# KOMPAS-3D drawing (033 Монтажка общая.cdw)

Referenced files in \\Promsrv4\спо\002_Проекты (ПСПД)\г. Тверь\Проекты жилые дома\Бобкова, 37\: Монтажка общая лист 55А.cdw
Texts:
  ПСПД-0000-2015
  Узел учета тепловой энергии, теплоносителя
  Ду65
  Ду50
  ИУСОп-65фс-50П-65фс-Ф65-01
  ИУСОо-65фс-50П-65фс-Ф65-01
  Направление потока**
  Стандартные изделия
  Переход К-57x5-32x3 ГОСТ 17378-2001
  Прокладка А-25-16-ПОН ГОСТ 15180-86
  Болт М6-6gx10.21.12Х18Н10Т ГОСТ 7798-70
  Переход
  ГОСТ 17378-2001
  Прокладка
  ГОСТ 15180-86
  А-25-16-ПОН
  Болт
  ГОСТ 7798-70
  М6-6gx10.21.12Х18Н10Т
  Узел учета тепловой энергии,
  теплоносителя
  Монтажный чертеж
  ЗАО "ПромСервис"
  ПСПД-0022-2015-
  Разраб.
  Чертеж строит. Первый лист. ГОСТ Р 21.1101-2009 Ф4.
  Лит-Масса-Масштаб
  Материал-Предприятие
  Масштаб
  Изм.
  Кол.уч.
  .Лист
  №док.
  Подп.
  Дата
  Стадия
  Лист
  Листов
  Изменение
  Номер документа
  Подпись
  Обозначение документа
  Наименование изделия и наименование документа
  Должность подписавшего
  Масса изделия
  Порядковый номер листа
  Общее количество листов в документе
  Индекс предприятия, выпускающего документ
  Инв. № подл.
  Подп. и дата
  Взам. инв. №
  Инвентарный номер подлинника
  Подпись принявшего подлинник на хранение
  Инвентарный номер подлинника, взамен которого выпущен данный подлинник
Dimensions and other numbers on the sheet: 2332*; 200; 200*; 250*; 100*; 290*; 2167*; 15180_86.vbs; 1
